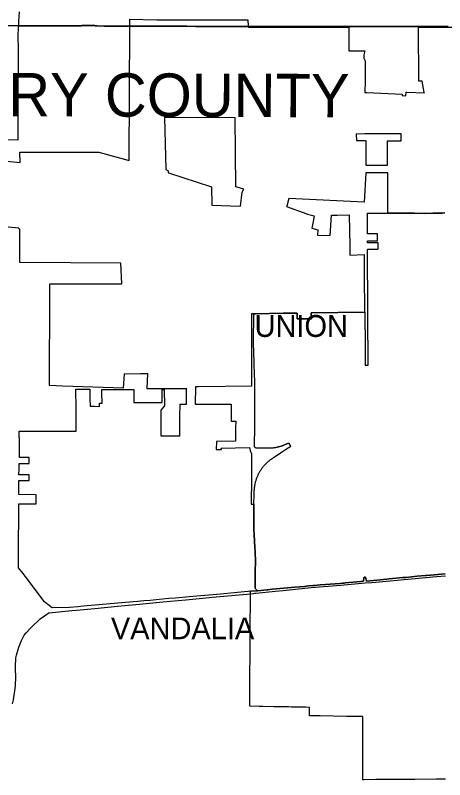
# Model space of a CAD drawing. Extents: x 0 to 34, y 0 to 22.
# Drawn here: x 4.9426 to 5.1018, y 15.846 to 16.1294 of the extents above; entities that cross this region are included whole.
import ezdxf

# ---------------------------------------------------------------- set-up
doc = ezdxf.new("R2010")
doc.units = 0
for name, color, linetype in [('GM_X_Corporation', 7, 'Continuous'), ('GM_X_Corporation_Text', 7, 'Continuous'), ('GM_X_County', 7, 'Continuous'), ('GM_X_County_Text', 7, 'Continuous'), ('GM_X_US_Route', 7, 'Continuous')]:
    doc.layers.add(name, color=color, linetype=linetype)

msp = doc.modelspace()

# ---------------------------------------------------------------- linework, layer by layer
at = {"layer": 'GM_X_Corporation'}
for points in [[(4.94401, 16.13064), (4.94373, 16.12716), (4.94369, 16.12548), (4.94366, 16.12508), (4.94364, 16.1249), (4.94361, 16.12431), (4.94358, 16.12373), (4.94356, 16.12283), (4.94356, 16.12222), (4.94356, 16.12162), (4.94358, 16.11691), (4.94358, 16.11688), (4.94358, 16.11671), (4.94358, 16.11559), (4.94359, 16.11446), (4.94359, 16.11246), (4.94357, 16.10682), (4.94356, 16.10577), (4.94356, 16.1018), (4.94355, 16.10131), (4.94349, 16.08314), (4.92053, 16.08368)], [(4.93939, 16.07527), (4.94437, 16.07477), (4.94423, 16.07863), (4.94438, 16.07863), (4.97352, 16.07871), (4.98482, 16.0756), (4.98499, 16.12537), (4.98499, 16.12792), (4.99499, 16.12776), (5.0012, 16.12773), (5.00752, 16.1277), (5.01089, 16.12768), (5.02195, 16.12766), (5.02883, 16.12767), (5.02885, 16.12531), (5.02885, 16.12507), (5.02885, 16.12504), (5.05331, 16.12505), (5.0533, 16.12496), (5.05848, 16.12496), (5.05848, 16.12504), (5.0662, 16.12503), (5.0662, 16.11626), (5.07216, 16.11624), (5.0718, 16.11478), (5.07182, 16.11352), (5.07225, 16.11253), (5.07225, 16.10528), (5.07223, 16.10076), (5.0729, 16.1008), (5.08607, 16.10017), (5.08605, 16.09961), (5.08742, 16.09955), (5.08742, 16.09963), (5.08747, 16.10089), (5.08776, 16.10088), (5.09424, 16.10067), (5.09422, 16.10079), (5.09349, 16.105), (5.09217, 16.105), (5.09205, 16.12499), (5.11475, 16.12496)], [(5.10183, 16.05612), (5.10098, 16.05611), (5.09734, 16.05604), (5.09422, 16.05597), (5.09064, 16.05599), (5.0887, 16.056), (5.08386, 16.05603), (5.0807, 16.05605), (5.0807, 16.05651), (5.0807, 16.05701), (5.08068, 16.06055), (5.08068, 16.06317), (5.08067, 16.0657), (5.08066, 16.06824), (5.08065, 16.07104), (5.07293, 16.071), (5.07259, 16.071), (5.07196, 16.06018), (5.044, 16.06144), (5.04321, 16.05867), (5.04317, 16.05851), (5.05064, 16.05585), (5.05095, 16.05574), (5.05338, 16.05507), (5.05296, 16.05302), (5.05246, 16.05055), (5.05472, 16.04988), (5.05463, 16.04787), (5.05932, 16.04779), (5.05983, 16.05532), (5.06196, 16.05535), (5.06636, 16.05541), (5.06656, 16.04391), (5.06662, 16.04054), (5.07198, 16.04075), (5.07198, 16.03344), (5.07199, 16.01934), (5.05247, 16.01907), (5.05233, 16.01906), (5.05239, 16.01699), (5.0524, 16.01694), (5.04709, 16.01688), (5.04702, 16.019), (5.04195, 16.01893), (5.03168, 16.01877), (5.03097, 16.01876), (5.03016, 16.01875), (5.03014, 15.99741), (5.03014, 15.9936), (5.03014, 15.99197), (5.01052, 15.99173), (5.00937, 15.99171), (5.00928, 15.98526), (5.01169, 15.98527), (5.01361, 15.98527), (5.0141, 15.98527), (5.01625, 15.98528), (5.01651, 15.98528), (5.01892, 15.98528), (5.02149, 15.98529), (5.02257, 15.98529), (5.02257, 15.98455), (5.02257, 15.98281), (5.02256, 15.98214), (5.02256, 15.97973), (5.02255, 15.97893), (5.02428, 15.97893), (5.02427, 15.97652), (5.02426, 15.97443), (5.02426, 15.97411), (5.02425, 15.97153), (5.01712, 15.97145), (5.017, 15.96842), (5.01897, 15.96842), (5.01896, 15.96898), (5.02944, 15.96915), (5.02946, 15.96902), (5.0295, 15.96885), (5.02953, 15.96868), (5.02957, 15.96851), (5.02961, 15.96834), (5.02966, 15.96817), (5.0297, 15.968), (5.02975, 15.96784), (5.02981, 15.96767), (5.02986, 15.96751), (5.02988, 15.96746), (5.02992, 15.96735), (5.02998, 15.96718), (5.03011, 15.96688), (5.03011, 15.96396), (5.03011, 15.96076), (5.0301, 15.9585), (5.03009, 15.95571), (5.03009, 15.95426), (5.03008, 15.95159), (5.03008, 15.94997), (5.03007, 15.94817), (5.03106, 15.94817), (5.03103, 15.94202), (5.03102, 15.94084), (5.03102, 15.93978), (5.03104, 15.93873), (5.03113, 15.93683), (5.03141, 15.93211), (5.03144, 15.93165), (5.03147, 15.93116), (5.03153, 15.93006), (5.03156, 15.92899), (5.03158, 15.92825), (5.03158, 15.92791), (5.03158, 15.92684), (5.03154, 15.92331), (5.03152, 15.92128), (5.03147, 15.91699), (5.03168, 15.91677), (5.03204, 15.9164), (5.03232, 15.91611), (5.02977, 15.91588), (5.02896, 15.91581), (5.02884, 15.9158), (5.01868, 15.91488), (5.00699, 15.91383), (5.00201, 15.91338), (4.99945, 15.91316), (4.99713, 15.91295), (4.99482, 15.91274), (4.99252, 15.91253), (4.99024, 15.91233), (4.98803, 15.91213), (4.98631, 15.91198), (4.96785, 15.91033), (4.96579, 15.91014), (4.96267, 15.90985), (4.95621, 15.90976), (4.95467, 15.91101), (4.95344, 15.912), (4.94655, 15.92098), (4.94543, 15.92245), (4.94376, 15.92463), (4.94377, 15.9247), (4.94378, 15.92776), (4.94379, 15.92895), (4.94388, 15.94832), (4.95027, 15.94831), (4.95029, 15.9517), (4.94389, 15.95171), (4.94391, 15.95494), (4.94392, 15.95698), (4.94772, 15.95699), (4.94772, 15.95909), (4.94393, 15.95908), (4.94394, 15.96126), (4.94395, 15.96328), (4.94411, 15.96328), (4.94773, 15.96329), (4.94774, 15.96329), (4.94774, 15.96332), (4.94775, 15.96547), (4.94412, 15.96546), (4.94413, 15.96683), (4.94413, 15.96748), (4.94414, 15.96949), (4.94412, 15.97283), (4.94398, 15.97283), (4.94396, 15.97525), (4.94679, 15.97526), (4.94779, 15.97526), (4.9506, 15.97527), (4.96519, 15.9753), (4.96519, 15.97529), (4.96516, 15.98453), (4.9651, 15.98643), (4.96506, 15.98772), (4.96504, 15.98804), (4.96495, 15.99084), (4.97015, 15.99078), (4.97024, 15.98745), (4.97032, 15.98447), (4.97088, 15.98446), (4.97204, 15.98445), (4.97376, 15.98443), (4.97373, 15.98562), (4.97404, 15.98562), (4.97479, 15.98561), (4.97468, 15.98946), (4.97465, 15.99074), (4.97529, 15.99073), (4.97571, 15.99072), (4.97866, 15.99069), (4.97869, 15.99069), (4.98122, 15.99067), (4.98165, 15.99067), (4.98403, 15.99067), (4.98648, 15.99067), (4.98654, 15.98583), (4.98891, 15.98583), (4.989, 15.98583), (4.99132, 15.98583), (4.99284, 15.98583), (4.99374, 15.98583), (4.99706, 15.98583), (4.99705, 15.99067), (4.99782, 15.99067), (4.99783, 15.98462), (4.99648, 15.98305), (4.99655, 15.97347), (5.00361, 15.9735), (5.0036, 15.97935), (5.00361, 15.98057), (5.00365, 15.98525), (5.00486, 15.98525), (5.00606, 15.98526), (5.00607, 15.98608), (5.0061, 15.99067), (5.00611, 15.99091), (5.00603, 15.99091), (4.99152, 15.99096), (4.99149, 15.99119), (4.99167, 15.99646), (4.98898, 15.9965), (4.98895, 15.9965), (4.98296, 15.99638), (4.98251, 15.99122), (4.96013, 15.99196), (4.95527, 15.99214), (4.95535, 16.02655), (4.95535, 16.02979), (4.95543, 16.02983), (4.98201, 16.02991), (4.98174, 16.03747), (4.94419, 16.03774), (4.94428, 16.05009), (4.94395, 16.05006), (4.94392, 16.05051), (4.91309, 16.05342)], [(5.10202, 15.92238), (5.09655, 15.92191), (5.09539, 15.9218), (5.095, 15.92176), (5.09468, 15.92173), (5.09463, 15.92173), (5.09161, 15.92144), (5.08743, 15.92105), (5.08632, 15.92095), (5.08117, 15.92046), (5.08035, 15.92038), (5.07904, 15.92026), (5.07276, 15.91967), (5.07245, 15.92114), (5.07244, 15.92114), (5.07198, 15.92112), (5.07197, 15.92091), (5.07182, 15.9209), (5.07171, 15.91958), (5.07072, 15.91949), (5.06485, 15.91897), (5.06446, 15.91894), (5.06397, 15.9189), (5.06292, 15.91881), (5.05764, 15.91839), (5.0556, 15.91823), (5.05358, 15.91807), (5.05291, 15.91802), (5.05131, 15.91787), (5.04977, 15.91772), (5.04806, 15.91757), (5.04798, 15.91756), (5.04627, 15.9174), (5.04212, 15.91701), (5.03786, 15.91662), (5.03622, 15.91647), (5.03599, 15.91644), (5.03232, 15.91611), (5.03204, 15.9164), (5.03168, 15.91677), (5.03147, 15.91699), (5.03152, 15.92128), (5.03154, 15.92331), (5.03158, 15.92684), (5.03158, 15.92791), (5.03158, 15.92825), (5.03156, 15.92899), (5.03153, 15.93006), (5.03147, 15.93116), (5.03144, 15.93165), (5.03141, 15.93211), (5.03113, 15.93683), (5.03104, 15.93873), (5.03102, 15.93978), (5.03102, 15.94084), (5.03103, 15.94202), (5.03106, 15.94818), (5.03117, 15.95185), (5.03117, 15.95233), (5.03117, 15.95263), (5.03118, 15.95293), (5.03119, 15.95323), (5.03121, 15.95352), (5.03123, 15.95382), (5.03126, 15.95412), (5.0313, 15.95442), (5.03134, 15.95471), (5.03135, 15.95479), (5.03138, 15.95501), (5.0314, 15.9551), (5.03143, 15.9553), (5.03145, 15.9554), (5.03149, 15.9556), (5.0315, 15.95565), (5.03151, 15.9557), (5.03162, 15.95621), (5.03168, 15.95646), (5.03175, 15.95672), (5.03182, 15.95697), (5.0319, 15.95722), (5.03198, 15.95747), (5.03206, 15.95769), (5.03207, 15.95772), (5.03216, 15.95796), (5.03225, 15.95821), (5.03235, 15.95845), (5.03245, 15.95869), (5.03256, 15.95893), (5.03267, 15.95917), (5.03279, 15.95941), (5.03291, 15.95964), (5.03303, 15.95987), (5.03316, 15.9601), (5.03329, 15.96033), (5.03342, 15.96055), (5.03356, 15.96078), (5.03371, 15.961), (5.03385, 15.96121), (5.03401, 15.96143), (5.03416, 15.96164), (5.03432, 15.96185), (5.03448, 15.96206), (5.03464, 15.96225), (5.03465, 15.96226), (5.03505, 15.96271), (5.03528, 15.96295), (5.03551, 15.96318), (5.03574, 15.96341), (5.03598, 15.96363), (5.03622, 15.96385), (5.03647, 15.96407), (5.03671, 15.96428), (5.03697, 15.96449), (5.03722, 15.96469), (5.03748, 15.96489), (5.03775, 15.96509), (5.03802, 15.96528), (5.03829, 15.96546), (5.0385, 15.9656), (5.03856, 15.96564), (5.04085, 15.96719), (5.0427, 15.96842), (5.04468, 15.96974), (5.04407, 15.97066), (5.0435, 15.97067), (5.04334, 15.97058), (5.04324, 15.97053), (5.04313, 15.97048), (5.04302, 15.97042), (5.04289, 15.97036), (5.04277, 15.9703), (5.04263, 15.97024), (5.04251, 15.97019), (5.04241, 15.97014), (5.04231, 15.9701), (5.04221, 15.97006), (5.04209, 15.97001), (5.04198, 15.96997), (5.04187, 15.96992), (5.04174, 15.96987), (5.04162, 15.96983), (5.04148, 15.96978), (5.04135, 15.96973), (5.04123, 15.96969), (5.04109, 15.96965), (5.04097, 15.96961), (5.04083, 15.96956), (5.04069, 15.96952), (5.04057, 15.96949), (5.04043, 15.96945), (5.04031, 15.96941), (5.0402, 15.96939), (5.04008, 15.96935), (5.03995, 15.96932), (5.0398, 15.96929), (5.03967, 15.96926), (5.03953, 15.96923), (5.0394, 15.9692), (5.03926, 15.96917), (5.03912, 15.96915), (5.03899, 15.96912), (5.03883, 15.9691), (5.03869, 15.96907), (5.03856, 15.96905), (5.03842, 15.96904), (5.03829, 15.96902), (5.03814, 15.969), (5.03802, 15.96899), (5.0379, 15.96897), (5.03779, 15.96896), (5.03768, 15.96895), (5.03757, 15.96894), (5.03747, 15.96894), (5.03738, 15.96893), (5.03727, 15.96892), (5.03717, 15.96892), (5.03706, 15.96891), (5.03691, 15.96891), (5.03676, 15.9689), (5.03661, 15.9689), (5.03645, 15.9689), (5.03627, 15.9689), (5.03219, 15.96892), (5.03209, 15.96892), (5.03204, 15.96892), (5.03201, 15.96892), (5.03197, 15.96893), (5.03193, 15.96894), (5.03189, 15.96894), (5.03185, 15.96896), (5.03181, 15.96897), (5.03178, 15.96898), (5.03175, 15.96899), (5.03172, 15.96901), (5.03169, 15.96903), (5.03166, 15.96904), (5.03163, 15.96906), (5.0316, 15.96908), (5.03157, 15.96911), (5.03154, 15.96913), (5.03151, 15.96916), (5.03149, 15.96919), (5.03146, 15.96922), (5.03144, 15.96925), (5.03142, 15.96928), (5.0314, 15.96932), (5.03138, 15.96935), (5.03136, 15.96939), (5.03135, 15.96942), (5.03133, 15.96945), (5.03132, 15.96949), (5.03131, 15.96953), (5.0313, 15.96957), (5.03129, 15.96961), (5.03129, 15.96965), (5.03129, 15.96969), (5.03129, 15.96972), (5.03129, 15.97023), (5.03129, 15.97071), (5.03133, 15.97599), (5.03137, 15.98076), (5.03139, 15.98397), (5.03141, 15.98719), (5.03142, 15.9904), (5.03137, 15.99362), (5.03128, 15.99633), (5.03123, 15.99742), (5.03114, 15.99935), (5.03108, 16.00073), (5.03093, 16.00794), (5.03097, 16.01876), (5.03168, 16.01877), (5.04195, 16.01893), (5.04702, 16.019), (5.04709, 16.01688), (5.0524, 16.01694), (5.05239, 16.01699), (5.05233, 16.01906), (5.05247, 16.01907), (5.07198, 16.01934), (5.07215, 16.01935), (5.07217, 16.01297), (5.07224, 16.01297), (5.07225, 16.01116), (5.07226, 16.00914), (5.07226, 16.00896), (5.07227, 16.00759), (5.07228, 16.00413), (5.07228, 16.00334), (5.07226, 16.00013), (5.07226, 15.9997), (5.07339, 15.99971), (5.07339, 16.00012), (5.0734, 16.00236), (5.07341, 16.00413), (5.07339, 16.00696), (5.07338, 16.00895), (5.07331, 16.00895), (5.07331, 16.00914), (5.0733, 16.01014), (5.07329, 16.01286), (5.07327, 16.0195), (5.07326, 16.02163), (5.07325, 16.02454), (5.07324, 16.02906), (5.07322, 16.03344), (5.07322, 16.03388), (5.07321, 16.03461), (5.07319, 16.04075), (5.07318, 16.04162), (5.07318, 16.04276), (5.07433, 16.04275), (5.07653, 16.04275), (5.07712, 16.04275), (5.07712, 16.04508), (5.07562, 16.04508), (5.07462, 16.04508), (5.07317, 16.04509), (5.07317, 16.04584), (5.07433, 16.04584), (5.07655, 16.04583), (5.07687, 16.04583), (5.07687, 16.04611), (5.07686, 16.04833), (5.07412, 16.04833), (5.07316, 16.04834), (5.07314, 16.05231), (5.07312, 16.0559), (5.07312, 16.05609), (5.07333, 16.05609), (5.0807, 16.05605), (5.08386, 16.05603), (5.0887, 16.056), (5.09064, 16.05599), (5.09421, 16.05597), (5.09734, 16.05604), (5.10098, 16.05611), (5.10183, 16.05612)], [(5.10204, 15.84627), (5.09871, 15.84626), (5.09866, 15.84626), (5.09075, 15.84614), (5.09068, 15.84614), (5.08887, 15.84613), (5.08706, 15.84612), (5.08525, 15.84611), (5.08344, 15.8461), (5.08163, 15.84609), (5.07982, 15.84608), (5.07801, 15.84607), (5.07777, 15.84607), (5.0762, 15.84607), (5.07195, 15.84605), (5.07162, 15.84604), (5.07146, 15.84604), (5.07146, 15.84782), (5.07147, 15.85181), (5.07147, 15.85277), (5.07148, 15.86334), (5.07148, 15.86428), (5.07149, 15.86829), (5.07149, 15.86884), (5.07149, 15.86908), (5.07149, 15.8692), (5.07149, 15.86942), (5.07085, 15.86943), (5.07085, 15.86943), (5.06543, 15.86951), (5.05557, 15.86966), (5.05163, 15.86972), (5.05163, 15.86985), (5.05162, 15.87286), (5.05032, 15.87288), (5.04553, 15.87297), (5.04501, 15.87298), (5.04381, 15.873), (5.04186, 15.87303), (5.03935, 15.87308), (5.03838, 15.8731), (5.03434, 15.87317), (5.03297, 15.87319), (5.02948, 15.87326), (5.02948, 15.87326), (5.02953, 15.88022), (5.02954, 15.88169), (5.02955, 15.88329), (5.02957, 15.88558), (5.02961, 15.89174), (5.02962, 15.89299), (5.02962, 15.89398), (5.02963, 15.89503), (5.02963, 15.89585), (5.02965, 15.89833), (5.02966, 15.89953), (5.02966, 15.89989), (5.02967, 15.90059), (5.02967, 15.90101), (5.02967, 15.90125), (5.02967, 15.90174), (5.02968, 15.90203), (5.0297, 15.90474), (5.0297, 15.90613), (5.02973, 15.90917), (5.02974, 15.91121), (5.02975, 15.91208), (5.02975, 15.91289), (5.02975, 15.91354), (5.02975, 15.91378), (5.02976, 15.91426), (5.02976, 15.91434), (5.02977, 15.91523), (5.02977, 15.91588), (5.03232, 15.91611), (5.03599, 15.91644), (5.03622, 15.91647), (5.03786, 15.91662), (5.04212, 15.91701), (5.04627, 15.9174), (5.04798, 15.91756), (5.04806, 15.91757), (5.04977, 15.91772), (5.05131, 15.91787), (5.05291, 15.91802), (5.05358, 15.91807), (5.0556, 15.91823), (5.05764, 15.91839), (5.06292, 15.91881), (5.06397, 15.9189), (5.06446, 15.91894), (5.06485, 15.91897), (5.07072, 15.91949), (5.07171, 15.91958), (5.07182, 15.9209), (5.07197, 15.92091), (5.07198, 15.92112), (5.07244, 15.92114), (5.07245, 15.92114), (5.07276, 15.91967), (5.07904, 15.92026), (5.08035, 15.92038), (5.08117, 15.92046), (5.08632, 15.92095), (5.08743, 15.92105), (5.09161, 15.92144), (5.09463, 15.92173), (5.09468, 15.92173), (5.095, 15.92176), (5.09655, 15.92191), (5.10202, 15.92238)]]:
    msp.add_lwpolyline(points, dxfattribs=at)
for points in [[(4.99835, 16.0722), (4.99918, 16.07188), (4.99931, 16.07104), (5.01527, 16.06579), (5.01546, 16.05899), (5.0261, 16.05867), (5.02668, 16.0638), (5.02726, 16.06495), (5.02431, 16.06585), (5.02412, 16.09136), (4.99783, 16.09149)], [(5.06903, 16.08296), (5.07224, 16.08295), (5.07258, 16.08292), (5.07257, 16.0766), (5.07258, 16.0738), (5.07292, 16.07381), (5.08064, 16.07384), (5.08063, 16.07664), (5.08062, 16.07874), (5.08061, 16.08109), (5.08061, 16.08292), (5.08386, 16.08292), (5.0846, 16.08292), (5.08569, 16.08292), (5.08569, 16.08509), (5.08568, 16.0855), (5.08552, 16.0855), (5.08294, 16.08549), (5.07991, 16.08549), (5.07288, 16.08548), (5.07256, 16.08549), (5.07223, 16.08541), (5.06898, 16.08539)]]:
    msp.add_lwpolyline(points, close=True, dxfattribs=at)
at = {"layer": 'GM_X_County'}
for points in [[(4.92395, 16.12579), (4.94355, 16.12552), (4.94414, 16.12549), (4.94998, 16.12546), (4.95431, 16.12546), (4.9618, 16.12545), (4.96454, 16.12546), (4.96645, 16.12543), (4.96656, 16.12543), (4.96677, 16.12545), (4.96691, 16.12547), (4.96709, 16.12551), (4.96726, 16.12556), (4.96743, 16.12566), (4.97186, 16.12563), (4.972, 16.12556), (4.97214, 16.12551), (4.97225, 16.12548), (4.97236, 16.12546), (4.97257, 16.12545), (4.97276, 16.12544), (4.97552, 16.12542), (4.98687, 16.12536), (4.99366, 16.12538), (4.99987, 16.12535), (5.00619, 16.12533), (5.00956, 16.1253), (5.02063, 16.12529), (5.02847, 16.1253), (5.0446, 16.12528), (5.04529, 16.12528), (5.04676, 16.12527), (5.04882, 16.12526), (5.05082, 16.12525), (5.05198, 16.12526), (5.05467, 16.12528), (5.05746, 16.12528), (5.05946, 16.12529), (5.06326, 16.1253), (5.06621, 16.12529), (5.07265, 16.12529), (5.07315, 16.12529), (5.08224, 16.12525), (5.08335, 16.12524), (5.08456, 16.12524), (5.08557, 16.12524), (5.08836, 16.12525), (5.09068, 16.12524), (5.09279, 16.12523), (5.09521, 16.12523), (5.09716, 16.12522), (5.09953, 16.12522), (5.1008, 16.12521), (5.10312, 16.12523)], [(5.10312, 16.12523), (5.1008, 16.12521), (5.09953, 16.12522), (5.09716, 16.12522), (5.09521, 16.12523), (5.09279, 16.12523), (5.09068, 16.12524), (5.08836, 16.12525), (5.08557, 16.12524), (5.08456, 16.12524), (5.08335, 16.12524), (5.08224, 16.12525), (5.07315, 16.12529), (5.07265, 16.12529), (5.06621, 16.12529), (5.06326, 16.1253), (5.05946, 16.12529), (5.05746, 16.12528), (5.05467, 16.12528), (5.05198, 16.12526), (5.05082, 16.12525), (5.04882, 16.12526), (5.04676, 16.12527), (5.04529, 16.12528), (5.0446, 16.12528), (5.02847, 16.1253), (5.02063, 16.12529), (5.00956, 16.1253), (5.00619, 16.12533), (4.99987, 16.12535), (4.99366, 16.12538), (4.98687, 16.12536), (4.97552, 16.12542), (4.97276, 16.12544), (4.97257, 16.12545), (4.97236, 16.12546), (4.97225, 16.12548), (4.97214, 16.12551), (4.972, 16.12556), (4.97186, 16.12563), (4.96743, 16.12566), (4.96726, 16.12556), (4.96709, 16.12551), (4.96691, 16.12547), (4.96677, 16.12545), (4.96656, 16.12543), (4.96645, 16.12543), (4.96454, 16.12546), (4.9618, 16.12545), (4.95431, 16.12546), (4.94998, 16.12546), (4.94414, 16.12549), (4.94355, 16.12552), (4.92395, 16.12579)]]:
    msp.add_lwpolyline(points, dxfattribs=at)
at = {"layer": 'GM_X_US_Route'}
for p, q in [((5.02976, 15.91498), (5.03096, 15.91509)), ((4.955, 15.90788), (4.96352, 15.90873)), ((4.96352, 15.90873), (4.96523, 15.9089))]:
    msp.add_line(p, q, dxfattribs=at)
for points in [[(5.07226, 15.91897), (5.07477, 15.9192), (5.08151, 15.91976), (5.0867, 15.92023)], [(5.0867, 15.92023), (5.09079, 15.92059), (5.09873, 15.92133), (5.10204, 15.92159)], [(5.03096, 15.91509), (5.03143, 15.91513), (5.03176, 15.91517), (5.03906, 15.91589), (5.04186, 15.91617), (5.05222, 15.91726), (5.06322, 15.91819), (5.07226, 15.91897)], [(4.96523, 15.9089), (4.972, 15.90956), (4.98041, 15.91035), (4.9886, 15.91114), (4.99733, 15.91203), (5.00578, 15.91275), (5.01442, 15.91364), (5.01561, 15.91373)], [(5.01561, 15.91373), (5.02267, 15.91427), (5.02976, 15.91498)], [(4.9481, 15.90207), (4.94907, 15.90304), (4.95131, 15.90518), (4.9518, 15.90562), (4.955, 15.90788)], [(4.94262, 15.88718), (4.94262, 15.88726), (4.9426, 15.88791), (4.94274, 15.89117), (4.94302, 15.89227), (4.94389, 15.89518), (4.94481, 15.89767), (4.94569, 15.89942), (4.94588, 15.89966), (4.94655, 15.90052), (4.9481, 15.90207)], [(4.94157, 15.87423), (4.9419, 15.87571), (4.94243, 15.87903), (4.94262, 15.88088), (4.94271, 15.88407), (4.94262, 15.88718)]]:
    msp.add_lwpolyline(points, dxfattribs=at)

# ---------------------------------------------------------------- texts
at = {"layer": 'GM_X_Corporation_Text'}
for s, p in [('UNION', (5.03127, 16.01026)), ('UNION', (5.03129, 16.01017)), ('VANDALIA', (4.97801, 15.89812))]:
    msp.add_text(s, height=0.008037, rotation=0, dxfattribs=at).set_placement(p)
at = {"layer": 'GM_X_County_Text'}
msp.add_text('MONTGOMERY COUNTY', height=0.016074, rotation=359.824, dxfattribs=at).set_placement((4.81096, 16.09235))

doc.saveas('drawing.dxf')
